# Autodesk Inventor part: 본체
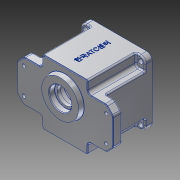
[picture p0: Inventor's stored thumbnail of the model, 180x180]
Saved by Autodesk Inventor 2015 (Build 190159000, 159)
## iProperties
Created: 2016-02
Part Number: 본체
Material: Aluminum 6061
Document SubType Name: Modeling
Designer: Administrator
Density: 2.7 g/cm^3
Appearance: Aluminum - Flat
Mass: 873.749 g
Surface Area: 761.178 cm^2
Volume: 323.611 cm^3
Author: Administrator
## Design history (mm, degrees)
sketch "Sketch1"
  geometry: L1 (-70, -30)-(70, -30); L2 (70, -30)-(70, 30); L3 (70, 30)-(-70, 30); L4 (-70, 30)-(-70, -30); L5 (-70, -30)-(70, 30); L6 (70, -30)-(-70, 30); 1 further point
  constraints: 12 end point, 2 midpoint, 2 parallel, 1 horizontal, 1 perpendicular
  dimensions: "d0" = 60 distance of L1.end L2.end; "d1" = 140 distance of L2.end L3.end
extrude "Extrusion1" new body sketch "Sketch1" distance "d2" = 13; taper "d3" = 0 deg
sketch "Sketch2"
  geometry: L1 (70, 30)-(-70, 30) reference; L2 (-70, 30)-(-70, -30) reference; L3 (-70, -30)-(70, -30) reference; L4 (70, -30)-(70, 30) reference; L5 (-33, 30)-(33, 30); L6 (33, 30)-(33, -30); L7 (33, -30)-(-33, -30); L8 (-33, -30)-(-33, 30); L9 (-33, 30)-(33, -30); L10 (33, 30)-(-33, -30); 1 further point
  constraints: 12 end point, 2 midpoint, 2 parallel, 1 collinear, 1 horizontal, 1 perpendicular
  dimensions: "d4" = 66 distance of L6.end L7.end
extrude "Extrusion2" join sketch "Sketch2" distance "d5" = 67; taper "d6" = 0 deg
sketch "Sketch3"
  geometry: L1 (-47, 47)-(47, 47); L2 (47, 47)-(47, -47); L3 (47, -47)-(-47, -47); L4 (-47, -47)-(-47, 47); L5 (-47, 47)-(47, -47); L6 (47, 47)-(-47, -47); 1 further point
  constraints: 12 end point, 2 midpoint, 2 parallel, 2 perpendicular, 1 horizontal
  dimensions: "d7" = 94 distance of L2.end L3.end
extrude "Extrusion3" join sketch "Sketch3" distance "d8" = 10; taper "d9" = 0 deg
sketch "Sketch4"
  geometry: L1 (33, -30)-(33, 30) reference; L2 (-33, 30)-(-33, -30) reference; L3 (33, 30)-(70, 30) reference; L4 (-70, 30)-(-33, 30) reference; L5 (70, -30)-(33, -30) reference; L6 (-33, -30)-(-70, -30) reference; L7 (-47, 47)-(-47, -47) reference; L8 (47, -47)-(47, 47) reference; L9 (-47, -30)-(-47, 30); L10 (-47, 30)-(-33, 30); L11 (-33, 30)-(-33, -30); L12 (-33, -30)-(-47, -30); L13 (33, -30)-(47, -30); L14 (47, -30)-(47, 30); L15 (47, 30)-(33, 30); L16 (33, 30)-(33, -30); 1 further point
  constraints: 16 end point, 6 point on line, 2 collinear, 2 parallel, 2 perpendicular, 1 horizontal
extrude "Extrusion4" join sketch "Sketch4" stored distance "d10" = 10; taper "d11" = 0 deg
sketch "Sketch5"
  geometry: L1 (33, -47)-(-33, -47); L2 (-33, -47)-(-33, 47); L3 (-33, 47)-(33, 47); L4 (33, 47)-(33, -47); L5 (33, -47)-(-33, 47); L6 (-33, -47)-(33, 47); L7 (47, 47)-(-47, 47) reference; L8 (-47, -47)-(47, -47) reference; 1 further point
  constraints: 12 end point, 2 midpoint, 2 parallel, 1 collinear, 1 horizontal, 1 perpendicular
  dimensions: "d12" = 66 distance of L2.end L3.end
extrude "Extrusion5" join sketch "Sketch5" stored distance "d13" = 10; taper "d14" = 0 deg
sketch "Sketch6"
  geometry: 2 further points
  constraints: 1 coincident
hole "Hole1" sketch "Sketch6" at (0, 0) diameter "d15" = 80; stored, may be unused: countersink angle "d19" = 90 deg, drill point angle "d21" = 0 deg; dims "d16" = 6, "d17" = 86, "d18" = 9, "d20" = 71
sketch "Sketch7"
  geometry: A1 r 21 centre (0, -11) between (-8.978, 7.984) and (8.978, 7.984); A2 r 15 centre (0, 20) between (8.978, 7.984) and (-8.978, 7.984); 1 further point
  constraints: 4 point on circle, 2 centre point, 2 vertical alignment
  dimensions: "d22" = 21 radius of A1; "d23" = 11 distance of point (0, 0) A1.centre; "d24" = 15 radius of A2; "d25" = 20 distance of A2.centre point (0, 0)
extrude "Extrusion6" join sketch "Sketch7" distance "d26" = 7; taper "d27" = 0 deg
sketch "Sketch8"
  geometry: C1 r 28 at (0, 11); A1 r 21 centre (0, 11) between (8.978, -7.984) and (-8.978, -7.984) reference; 1 further point
  constraints: 1 centre point, 1 coincident
  dimensions: "d28" = 56 diameter of C1
extrude "Extrusion7" join sketch "Sketch8" distance "d29" = 7; taper "d30" = -10 deg
hole "Hole2" diameter "d33" = 25; stored, may be unused: countersink angle "d37" = 90 deg, drill point angle "d39" = 0 deg; dims "d31" = 10, "d32" = 10, "d34" = 6, "d35" = 32, "d36" = 8, "d38" = 13
hole "Hole3" diameter "d42" = 35; stored, may be unused: countersink angle "d46" = 90 deg, drill point angle "d48" = 0 deg; dims "d40" = 10, "d41" = 10, "d43" = 6, "d44" = 32, "d45" = 8, "d47" = 10
hole "Hole4" diameter "d51" = 19; stored, may be unused: countersink angle "d55" = 90 deg, drill point angle "d57" = 0 deg; dims "d49" = 10, "d50" = 10, "d52" = 6, "d53" = 22, "d54" = 7, "d56" = 8
sketch "Sketch11"
  geometry: L1 (36, 0)-(-36, 0); L2 (35.777, -4)-(39.799, -4); L3 (35.777, 4)-(39.799, 4); L4 (-35.777, -4)-(-39.799, -4); L5 (-35.777, 4)-(-39.799, 4); A1 r 36 centre (0, 0) between (36, 0) and (-36, 0); A2 r 40 centre (0, 0) between (39.799, -4) and (39.799, 4) reference; A3 r 4 centre (36, 0) between (36, 4) and (36, -4); A4 r 4 centre (-36, 0) between (-36, -4) and (-36, 4); A5 r 40 centre (0, 0) between (39.799, -4) and (39.799, 4); A6 r 40 centre (0, 0) between (-39.799, 4) and (-39.799, -4); 1 further point
  constraints: 18 point on circle, 10 end point, 5 centre point, 5 coincident, 5 horizontal, 4 point on line, 4 tangent, 1 midpoint
  dimensions: "d64" = 36 radius of A1; "d65" = 4 radius of A3; "d66" = 4 radius of A4
extrude "Extrusion9" join sketch "Sketch11" stored distance "d67" = 7; taper "d68" = 0 deg
sketch "Sketch13"
  geometry: L1 (-60, 19)-(60, 19); L2 (60, 19)-(60, -19); L3 (60, -19)-(-60, -19); L4 (-60, -19)-(-60, 19); L5 (-60, 19)-(60, -19); L6 (60, 19)-(-60, -19); 5 further points
  constraints: 12 end point, 4 coincident, 2 midpoint, 2 parallel, 1 horizontal, 1 perpendicular
  dimensions: "d71" = 38 distance of L1.end L2.end; "d72" = 120 distance of L2.end L3.end
hole "Hole5" sketch "Sketch13" at (60, -19), (60, 19), (-60, 19), (-60, -19) diameter "d73" = 5; stored, may be unused: countersink angle "d77" = 90 deg, drill point angle "d79" = 0 deg; dims "d74" = 6, "d75" = 9, "d76" = 4, "d78" = 13
sketch "Sketch14"
  geometry: L1 (40, -40)-(-40, -40); L2 (-40, -40)-(-40, 40); L3 (-40, 40)-(40, 40); L4 (40, 40)-(40, -40); L5 (40, -40)-(-40, 40); L6 (-40, -40)-(40, 40); C1 r 3.5 at (-40, 40); C2 r 3.5 at (-40, -40); C3 r 3.5 at (40, -40); C4 r 3.5 at (40, 40); 1 further point
  constraints: 12 end point, 4 centre point, 4 coincident, 3 equal radius, 2 midpoint, 2 parallel, 1 horizontal, 1 perpendicular
  dimensions: "d80" = 80 distance of L3.end L1.start; "d81" = 80 distance of L2.end L3.end; "d82" = 7 diameter of C1
extrude "Extrusion10" cut sketch "Sketch14" stored distance "d83" = 7; taper "d84" = 0 deg
hole "Hole6" diameter "d87" = 3.242; stored, may be unused: countersink angle "d91" = 90 deg, drill point angle "d93" = 118 deg; dims "d85" = 10, "d86" = 10, "d88" = 7, "d89" = 9, "d90" = 4, "d92" = 9
hole "Hole7" diameter "d96" = 3.242; stored, may be unused: countersink angle "d100" = 90 deg, drill point angle "d102" = 118 deg; dims "d94" = 10, "d95" = 10, "d97" = 7, "d98" = 9, "d99" = 4, "d101" = 9
sketch "Sketch15" dims "d0" = 60, "d1" = 140
  geometry: L1 (94, 0)-(0, 0) reference; L2 (14, -80)-(80, -80) reference; 3 further points
  constraints: 1 midpoint, 1 vertical alignment, 1 other
  dimensions: "d103" = 40 distance from line of L1 point (47, -40)
emboss "Emboss1" sketch "Sketch15" dims "d0" = 60, "d1" = 140, "d104" = 0.5, "d105" = 0
chamfer "Chamfer1" distance "d106" = 10; stored, may be unused: second distance "d107" = 2, angle "d108" = 45 deg
fillet "Fillet1" dims "d109" = 3.5
fillet "Fillet2" dims "d110" = 3
fillet "Fillet3" dims "d111" = 8
fillet "Fillet4" dims "d112" = 5
fillet "Fillet6" dims "d114" = 5
sketch "Sketch16"
  geometry: L1 (-61.464, 28.536)-(-68.536, 21.464) reference; L2 (-70, -17.929)-(-70, 17.929) reference; L3 (-68.536, -21.464)-(-61.464, -28.536) reference; L4 (-47, -30)-(-57.929, -30) reference; L5 (-47, -30)-(-38, -30) reference; L6 (-33, -47)-(-33, -35) reference; L7 (-39, -47)-(39, -47) reference; L8 (33, -35)-(33, -47) reference; L9 (38, -30)-(47, -30) reference; L10 (57.929, -30)-(47, -30) reference; L11 (61.464, -28.536)-(68.536, -21.464) reference; L12 (70, 17.929)-(70, -17.929) reference; L13 (68.536, 21.464)-(61.464, 28.536) reference; L14 (47, 30)-(57.929, 30) reference; L15 (38, 30)-(47, 30) reference; L16 (33, 47)-(33, 35) reference; L17 (39, 47)-(-39, 47) reference; L18 (33, 47)-(-33, 47); L19 (-33, 35)-(-33, 47) reference; L20 (-47, 30)-(-38, 30) reference; L21 (-57.929, 30)-(-47, 30) reference; L22 (33, -47)-(-33, -47); L23 (32, -46)-(32, -35); L24 (38, -29)-(47, -29); L25 (47, -29)-(57.929, -29); L26 (60.757, -27.828)-(67.828, -20.757); L27 (69, -17.929)-(69, 17.929); L28 (67.828, 20.757)-(60.757, 27.828); L29 (57.929, 29)-(47, 29); L30 (47, 29)-(38, 29); L31 (32, 35)-(32, 46); L32 (-32, 46)-(-32, 35); L33 (-38, 29)-(-47, 29); L34 (-47, 29)-(-57.929, 29); L35 (-60.757, 27.828)-(-67.828, 20.757); L36 (-69, 17.929)-(-69, -17.929); L37 (-67.828, -20.757)-(-60.757, -27.828); L38 (-57.929, -29)-(-47, -29); L39 (-47, -29)-(-38, -29); L40 (-32, -35)-(-32, -46); L41 (32, -46)-(-32, -46); L42 (32, 46)-(-32, 46); A1 r 5 centre (-57.929, 25) between (-57.929, 30) and (-61.464, 28.536) reference; A2 r 5 centre (-65, 17.929) between (-68.536, 21.464) and (-70, 17.929) reference; A3 r 5 centre (-65, -17.929) between (-70, -17.929) and (-68.536, -21.464) reference; A4 r 5 centre (-57.929, -25) between (-61.464, -28.536) and (-57.929, -30) reference; A5 r 5 centre (-38, -35) between (-33, -35) and (-38, -30) reference; A6 r 5 centre (38, -35) between (38, -30) and (33, -35) reference; A7 r 5 centre (57.929, -25) between (57.929, -30) and (61.464, -28.536) reference; A8 r 5 centre (65, -17.929) between (68.536, -21.464) and (70, -17.929) reference; A9 r 5 centre (65, 17.929) between (70, 17.929) and (68.536, 21.464) reference; A10 r 5 centre (57.929, 25) between (61.464, 28.536) and (57.929, 30) reference; A11 r 5 centre (38, 35) between (33, 35) and (38, 30) reference; A12 r 5 centre (-38, 35) between (-38, 30) and (-33, 35) reference; A13 r 6 centre (38, -35) between (38, -29) and (32, -35); A14 r 4 centre (57.929, -25) between (57.929, -29) and (60.757, -27.828); A15 r 4 centre (65, -17.929) between (67.828, -20.757) and (69, -17.929); A16 r 4 centre (65, 17.929) between (69, 17.929) and (67.828, 20.757); A17 r 4 centre (57.929, 25) between (60.757, 27.828) and (57.929, 29); A18 r 6 centre (38, 35) between (32, 35) and (38, 29); A19 r 6 centre (-38, 35) between (-38, 29) and (-32, 35); A20 r 4 centre (-57.929, 25) between (-57.929, 29) and (-60.757, 27.828); A21 r 4 centre (-65, 17.929) between (-67.828, 20.757) and (-69, 17.929); A22 r 4 centre (-65, -17.929) between (-69, -17.929) and (-67.828, -20.757); A23 r 4 centre (-57.929, -25) between (-60.757, -27.828) and (-57.929, -29); A24 r 6 centre (-38, -35) between (-32, -35) and (-38, -29); 1 further point
  constraints: 44 end point, 24 point on circle, 12 centre point, 2 parallel, 1 collinear, 1 horizontal, 24 other
  dimensions: "d115" = 1 distance between parallel lines of L7 L41; "d116" = 1 distance between parallel lines of L9 L24; "d117" = 1 distance between parallel lines of L16 L31; "d118" = 1 distance between parallel lines of L17 L42; "d119" = 1 radial gap between concentric circles of A12 A19; "d120" = 1 distance between parallel lines of L19 L32; "d121" = 1 distance between parallel lines of L6 L40; "d122" = 1 distance between parallel lines of L8 L23
extrude "Extrusion11" cut sketch "Sketch16" distance "d123" = 1; taper "d124" = 0 deg
fillet "Fillet7" dims "d125" = 0.3
fillet "Fillet8" dims "d126" = 2
chamfer "Chamfer2" distance "d127" = 1; stored, may be unused: second distance "d128" = 2, angle "d129" = 45 deg
body "Solid1"
node "Projected Loop1"
